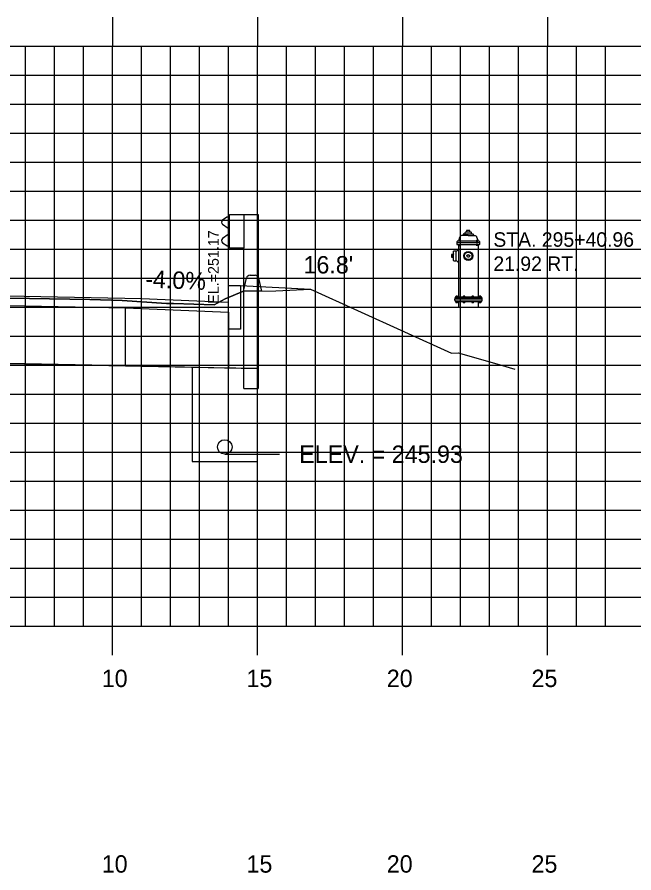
# Model space of a CAD drawing. Extents: x 859575 to 859745, y 366268 to 366378.
# Drawn here: x 859664.5 to 859685.77, y 366298.73 to 366328.24 of the extents above; entities that cross this region are included whole.
import ezdxf

# ---------------------------------------------------------------- set-up
doc = ezdxf.new("R2010")
doc.units = 0
for name, color, linetype in [('ANNOTATION', 7, 'Continuous'), ('D_Curb_Type_1_Rt', 7, 'Continuous'), ('D_Roadway_Edge_Shoulder', 7, 'Continuous'), ('D_Roadway_FinishedGrade', 7, 'Continuous'), ('D_Roadway_SubGrade', 7, 'Continuous'), ('D_Text_Monospaced', 7, 'Continuous'), ('D_Text_Standard', 7, 'Continuous'), ('H_V ANNOTATION', 7, 'Continuous'), ('JUNK COM EXC', 7, 'Continuous'), ('junk strct exc', 7, 'Continuous'), ('MAJOR', 7, 'Continuous'), ('MINOR', 7, 'Continuous'), ('PDRAIN', 7, 'Continuous'), ('S_Curb_Type_3', 7, 'Continuous'), ('S_Guardrail_Beam', 7, 'Continuous'), ('S_Roadway_Centerline', 7, 'Continuous'), ('S_Utilities_Hydrant', 7, 'Continuous')]:
    doc.layers.add(name, color=color, linetype=linetype)

msp = doc.modelspace()

# ---------------------------------------------------------------- linework, layer by layer
at = {"layer": 'D_Curb_Type_1_Rt'}
msp.add_lwpolyline([(859672.208, 366318.982), (859672.208, 366317.482), (859671.791, 366317.482), (859671.791, 366318.982)], close=True, dxfattribs=at)
at = {"layer": 'D_Roadway_Edge_Shoulder'}
msp.add_lwpolyline([(859642.824, 366318.371), (859646.797, 366318.53), (859657.797, 366318.75), (859668.797, 366318.53), (859671.791, 366318.41)], dxfattribs=at)
at = {"layer": 'D_Roadway_FinishedGrade'}
msp.add_lwpolyline([(859672.208, 366318.982), (859674.627, 366318.855)], dxfattribs=at)
at = {"layer": 'D_Roadway_SubGrade'}
for points in [[(859672.79, 366318.97), (859672.79, 366316.116), (859671.797, 366316.136)], [(859668.239, 366316.208), (859657.797, 366316.417), (859646.797, 366316.197), (859646.797, 366318.197), (859657.797, 366318.417), (859668.239, 366318.208)]]:
    msp.add_lwpolyline(points, dxfattribs=at)
msp.add_lwpolyline([(859668.239, 366318.208), (859671.791, 366318.065), (859671.791, 366316.136), (859668.239, 366316.208)], close=True, dxfattribs=at)
at = {"layer": 'D_Text_Standard'}
msp.add_lwpolyline([(859671.665, 366313.166), (859672.873, 366313.166), (859673.553, 366313.166)], dxfattribs=at)
at = {"layer": 'JUNK COM EXC'}
for points in [[(859668.239, 366316.208), (859672.79, 366316.116), (859672.79, 366318.798), (859672.312, 366318.793), (859671.68, 366318.518), (859671.301, 366318.317), (859669.901, 366318.359), (859669.657, 366318.367), (859668.133, 366318.467), (859667.018, 366318.498), (859657.962, 366318.648)], [(859657.797, 366316.417), (859668.239, 366316.208)]]:
    msp.add_lwpolyline(points, dxfattribs=at)
at = {"layer": 'junk strct exc'}
msp.add_lwpolyline([(859670.54, 366316.161), (859670.54, 366312.916), (859672.79, 366312.916), (859672.79, 366316.116)], close=True, dxfattribs=at)
at = {"layer": 'MAJOR'}
for p, q in [((859667.797, 366328.238), (859667.797, 366327.236)), ((859672.797, 366328.238), (859672.797, 366327.236)), ((859677.797, 366328.238), (859677.797, 366327.236)), ((859682.797, 366328.238), (859682.797, 366327.236)), ((859587.797, 366327.236), (859727.797, 366327.236)), ((859587.797, 366327.236), (859727.797, 366327.236)), ((859667.797, 366307.236), (859667.797, 366327.236)), ((859672.797, 366307.236), (859672.797, 366327.236)), ((859677.797, 366307.236), (859677.797, 366327.236)), ((859682.797, 366307.236), (859682.797, 366327.236)), ((859587.797, 366322.236), (859727.797, 366322.236)), ((859587.797, 366317.236), (859727.797, 366317.236)), ((859587.797, 366312.236), (859727.797, 366312.236)), ((859587.797, 366307.236), (859727.797, 366307.236)), ((859587.797, 366307.236), (859727.797, 366307.236)), ((859667.797, 366306.234), (859667.797, 366307.236)), ((859672.797, 366306.234), (859672.797, 366307.236)), ((859677.797, 366306.234), (859677.797, 366307.236)), ((859682.797, 366306.234), (859682.797, 366307.236))]:
    msp.add_line(p, q, dxfattribs=at)
at = {"layer": 'MINOR'}
for p, q in [((859664.797, 366307.236), (859664.797, 366327.236)), ((859665.797, 366307.236), (859665.797, 366327.236)), ((859666.797, 366307.236), (859666.797, 366327.236)), ((859668.797, 366307.236), (859668.797, 366327.236)), ((859669.797, 366307.236), (859669.797, 366327.236)), ((859670.797, 366307.236), (859670.797, 366327.236)), ((859671.797, 366307.236), (859671.797, 366327.236)), ((859673.797, 366307.236), (859673.797, 366327.236)), ((859674.797, 366307.236), (859674.797, 366327.236)), ((859675.797, 366307.236), (859675.797, 366327.236)), ((859676.797, 366307.236), (859676.797, 366327.236)), ((859678.797, 366307.236), (859678.797, 366327.236)), ((859679.797, 366307.236), (859679.797, 366327.236)), ((859680.797, 366307.236), (859680.797, 366327.236)), ((859681.797, 366307.236), (859681.797, 366327.236)), ((859683.797, 366307.236), (859683.797, 366327.236)), ((859684.797, 366307.236), (859684.797, 366327.236)), ((859587.797, 366326.236), (859727.797, 366326.236)), ((859587.797, 366325.236), (859727.797, 366325.236)), ((859587.797, 366324.236), (859727.797, 366324.236)), ((859587.797, 366323.236), (859727.797, 366323.236)), ((859587.797, 366321.236), (859727.797, 366321.236)), ((859587.797, 366320.236), (859727.797, 366320.236)), ((859587.797, 366319.236), (859727.797, 366319.236)), ((859587.797, 366318.236), (859727.797, 366318.236)), ((859587.797, 366316.236), (859727.797, 366316.236)), ((859587.797, 366315.236), (859727.797, 366315.236)), ((859587.797, 366314.236), (859727.797, 366314.236)), ((859587.797, 366313.236), (859727.797, 366313.236)), ((859587.797, 366311.236), (859727.797, 366311.236)), ((859587.797, 366310.236), (859727.797, 366310.236)), ((859587.797, 366309.236), (859727.797, 366309.236)), ((859587.797, 366308.236), (859727.797, 366308.236))]:
    msp.add_line(p, q, dxfattribs=at)
at = {"layer": 'PDRAIN'}
msp.add_lwpolyline([(859670.54, 366316.161), (859670.54, 366312.916), (859672.79, 366312.916), (859672.79, 366316.116)], dxfattribs=at)
msp.add_circle((859671.665, 366313.416), 0.25, dxfattribs=at)
at = {"layer": 'S_Curb_Type_3'}
for points in [[(859672.834, 366319.238), (859672.937, 366318.793), (859672.312, 366318.793), (859672.414, 366319.238)], [(859672.536, 366319.335), (859672.712, 366319.335)]]:
    msp.add_lwpolyline(points, dxfattribs=at)
for centre, start, end in [((859672.536, 366319.21), 90, 167.0054), ((859672.712, 366319.21), 12.9946, 90)]:
    msp.add_arc(centre, 0.125, start, end, dxfattribs=at)
at = {"layer": 'S_Guardrail_Beam'}
for p, q in [((859671.832, 366321.433), (859672.321, 366321.433)), ((859671.832, 366320.266), (859671.832, 366321.433)), ((859672.321, 366321.433), (859672.813, 366321.433)), ((859672.321, 366321.433), (859672.321, 366320.266)), ((859672.813, 366321.433), (859672.813, 366315.433)), ((859671.733, 366321.339), (859671.59, 366321.239)), ((859671.832, 366321.36), (859671.75, 366321.345)), ((859671.59, 366321.095), (859671.785, 366320.959)), ((859671.819, 366320.895), (859671.819, 366320.804)), ((859671.785, 366320.739), (859671.59, 366320.603)), ((859671.59, 366320.46), (859671.733, 366320.36)), ((859671.75, 366320.353), (859671.832, 366320.339)), ((859672.321, 366320.266), (859671.832, 366320.266)), ((859672.321, 366315.433), (859672.321, 366320.266)), ((859672.321, 366315.433), (859672.813, 366315.433))]:
    msp.add_line(p, q, dxfattribs=at)
for centre, major_axis, start_param, end_param in [((859671.64, 366321.167), (-0.0877, 0), 5.323254, 7.243116), ((859671.757, 366321.305), (-0.0417, 0), 4.886922, 5.323254), ((859671.74, 366320.895), (0.0789, 0), 0, 0.959931), ((859671.64, 366320.532), (-0.0877, 0), 5.323254, 7.243116), ((859671.74, 366320.804), (0.0789, 0), 5.323254, 6.283185), ((859671.757, 366320.394), (-0.0417, 0), 0.959931, 1.396263)]:
    msp.add_ellipse(centre, major_axis=major_axis, ratio=0.995501, start_param=start_param, end_param=end_param, dxfattribs=at)
at = {"layer": 'S_Roadway_Centerline'}
msp.add_lwpolyline([(859657.962, 366318.648), (859667.018, 366318.498), (859668.133, 366318.467), (859669.657, 366318.367), (859669.901, 366318.359), (859671.301, 366318.317), (859671.68, 366318.518), (859672.312, 366318.793), (859673.422, 366318.804), (859674.627, 366318.855), (859679.478, 366316.646), (859679.714, 366316.666), (859680.968, 366316.307), (859681.666, 366316.104)], dxfattribs=at)
at = {"layer": 'S_Utilities_Hydrant'}
for p, q in [((859679.763, 366320.638), (859679.724, 366320.51)), ((859680.062, 366320.709), (859679.831, 366320.709)), ((859679.909, 366320.765), (859680.214, 366320.765)), ((859679.949, 366320.806), (859679.949, 366320.765)), ((859680.158, 366320.822), (859679.966, 366320.821)), ((859680.062, 366320.709), (859680.293, 366320.709)), ((859680.174, 366320.765), (859680.174, 366320.806)), ((859680.361, 366320.638), (859680.4, 366320.51)), ((859679.668, 366320.494), (859679.668, 366320.413)), ((859680.457, 366320.453), (859679.668, 366320.453)), ((859680.44, 366320.51), (859679.684, 366320.51)), ((859679.724, 366320.397), (859679.724, 366318.591)), ((859679.743, 366320.51), (859679.743, 366320.527)), ((859679.743, 366320.373), (859679.743, 366320.397)), ((859679.772, 366320.527), (859679.772, 366320.51)), ((859679.772, 366320.397), (859679.772, 366320.373)), ((859680.353, 366320.527), (859680.353, 366320.51)), ((859680.353, 366320.397), (859680.353, 366320.373)), ((859680.381, 366320.51), (859680.381, 366320.527)), ((859680.381, 366320.373), (859680.381, 366320.397)), ((859680.4, 366320.397), (859680.4, 366318.591)), ((859679.521, 366320.051), (859679.521, 366320.048)), ((859679.521, 366320.048), (859679.521, 366319.958)), ((859679.521, 366319.955), (859679.521, 366319.958)), ((859679.531, 366320.063), (859679.531, 366319.942)), ((859679.536, 366320.064), (859679.536, 366319.942)), ((859679.556, 366320.07), (859679.548, 366320.069)), ((859679.556, 366319.845), (859679.556, 366320.162)), ((859679.572, 366320.177), (859679.633, 366320.177)), ((859679.633, 366320.177), (859679.633, 366319.828)), ((859679.64, 366320.167), (859679.633, 366320.167)), ((859679.64, 366319.834), (859679.64, 366320.172)), ((859679.724, 366320.239), (859679.724, 366320.239)), ((859679.556, 366319.935), (859679.548, 366319.937)), ((859679.633, 366319.828), (859679.571, 366319.828)), ((859679.64, 366319.839), (859679.633, 366319.839)), ((859679.724, 366319.767), (859679.724, 366319.767)), ((859680.543, 366318.534), (859679.592, 366318.534)), ((859680.543, 366318.478), (859679.592, 366318.478)), ((859679.617, 366318.591), (859680.518, 366318.591)), ((859679.652, 366318.608), (859679.652, 366318.591)), ((859679.68, 366318.591), (859679.68, 366318.608)), ((859679.903, 366318.608), (859679.903, 366318.591)), ((859679.932, 366318.591), (859679.932, 366318.608)), ((859680.204, 366318.608), (859680.204, 366318.591)), ((859680.231, 366318.591), (859680.231, 366318.608)), ((859680.455, 366318.608), (859680.455, 366318.591)), ((859680.483, 366318.591), (859680.483, 366318.608)), ((859680.518, 366318.421), (859679.617, 366318.421)), ((859679.652, 366318.421), (859679.652, 366318.397)), ((859679.68, 366318.397), (859679.68, 366318.421)), ((859679.724, 366318.421), (859679.724, 366318.255)), ((859679.903, 366318.421), (859679.903, 366318.397)), ((859679.932, 366318.397), (859679.932, 366318.421)), ((859680.204, 366318.421), (859680.204, 366318.397)), ((859680.231, 366318.397), (859680.231, 366318.421)), ((859680.4, 366318.421), (859680.4, 366318.255)), ((859680.455, 366318.421), (859680.455, 366318.397)), ((859680.483, 366318.397), (859680.483, 366318.421))]:
    msp.add_line(p, q, dxfattribs=at)
for points in [[(859680.119, 366320.821), (859680.119, 366320.877), (859680.006, 366320.877), (859680.006, 366320.821)], [(859679.893, 366320.709), (859679.893, 366320.75), (859679.894, 366320.75), (859679.893, 366320.75)], [(859680.231, 366320.75), (859680.23, 366320.75), (859680.231, 366320.75), (859680.231, 366320.709)], [(859679.683, 366320.396), (859679.683, 366320.397), (859680.441, 366320.397), (859680.441, 366320.396)], [(859679.73, 366320.51), (859679.73, 366320.527), (859679.733, 366320.531), (859679.782, 366320.531), (859679.785, 366320.527), (859679.785, 366320.51), (859679.73, 366320.51)], [(859679.785, 366320.397), (859679.785, 366320.373), (859679.782, 366320.369), (859679.733, 366320.369), (859679.73, 366320.373), (859679.73, 366320.397), (859679.785, 366320.397)], [(859679.743, 366320.376), (859679.743, 366320.36), (859679.772, 366320.36), (859679.772, 366320.373)], [(859680.395, 366320.51), (859680.395, 366320.527), (859680.391, 366320.531), (859680.342, 366320.531), (859680.338, 366320.527), (859680.338, 366320.51), (859680.395, 366320.51)], [(859680.338, 366320.397), (859680.338, 366320.373), (859680.342, 366320.369), (859680.391, 366320.369), (859680.395, 366320.373), (859680.395, 366320.397), (859680.338, 366320.397)], [(859680.381, 366320.376), (859680.381, 366320.36), (859680.353, 366320.36), (859680.353, 366320.373)], [(859680.457, 366320.413), (859680.457, 366320.493), (859680.457, 366320.494)], [(859679.521, 366320.048), (859679.485, 366320.048), (859679.485, 366319.958), (859679.521, 366319.958)], [(859680.094, 366319.959), (859680.03, 366319.959), (859680.01, 366320.02), (859680.062, 366320.058), (859680.114, 366320.02), (859680.094, 366319.959)], [(859679.694, 366318.591), (859679.694, 366318.608), (859679.69, 366318.612), (859679.642, 366318.612), (859679.638, 366318.608), (859679.638, 366318.591), (859679.694, 366318.591)], [(859679.945, 366318.591), (859679.945, 366318.608), (859679.941, 366318.612), (859679.893, 366318.612), (859679.889, 366318.608), (859679.889, 366318.591), (859679.945, 366318.591)], [(859680.246, 366318.591), (859680.246, 366318.608), (859680.242, 366318.612), (859680.193, 366318.612), (859680.189, 366318.608), (859680.189, 366318.591), (859680.246, 366318.591)], [(859680.497, 366318.591), (859680.497, 366318.608), (859680.494, 366318.612), (859680.445, 366318.612), (859680.441, 366318.608), (859680.441, 366318.591), (859680.497, 366318.591)], [(859679.638, 366318.421), (859679.638, 366318.397), (859679.642, 366318.394), (859679.69, 366318.394), (859679.694, 366318.397), (859679.694, 366318.421), (859679.638, 366318.421)], [(859679.68, 366318.4), (859679.68, 366318.384), (859679.652, 366318.384), (859679.652, 366318.397)], [(859679.889, 366318.421), (859679.889, 366318.397), (859679.893, 366318.394), (859679.941, 366318.394), (859679.945, 366318.397), (859679.945, 366318.421), (859679.889, 366318.421)], [(859679.932, 366318.4), (859679.932, 366318.384), (859679.903, 366318.384), (859679.903, 366318.397)], [(859680.189, 366318.421), (859680.189, 366318.397), (859680.193, 366318.394), (859680.242, 366318.394), (859680.246, 366318.397), (859680.246, 366318.421), (859680.189, 366318.421)], [(859680.231, 366318.4), (859680.231, 366318.384), (859680.204, 366318.384), (859680.204, 366318.397)], [(859680.441, 366318.421), (859680.441, 366318.397), (859680.445, 366318.394), (859680.494, 366318.394), (859680.497, 366318.397), (859680.497, 366318.421), (859680.441, 366318.421)], [(859680.483, 366318.4), (859680.483, 366318.384), (859680.455, 366318.384), (859680.455, 366318.397)]]:
    msp.add_lwpolyline(points, dxfattribs=at)
for radius in [0.158, 0.128]:
    msp.add_circle((859680.062, 366320.003), radius, dxfattribs=at)
for centre, radius, start, end in [((859679.855, 366320.617), 0.0943, 104.4243, 167.4801), ((859679.912, 366320.746), 0.0191, 96.9921, 168.8028), ((859679.968, 366320.802), 0.019, 96.6009, 168.4116), ((859680.156, 366320.802), 0.0191, 11.1972, 83.0079), ((859680.212, 366320.746), 0.019, 11.5319, 83.3426), ((859680.269, 366320.617), 0.0943, 12.5199, 75.5757), ((859679.687, 366320.491), 0.0191, 96.9921, 168.8028), ((859679.687, 366320.415), 0.0191, 186.9921, 258.8028), ((859679.736, 366320.522), 0.00826, 32.9144, 129.4939), ((859679.736, 366320.377), 0.00826, 230.5064, 327.0859), ((859679.757, 366320.503), 0.0282, 60.0007, 120.0007), ((859679.757, 366320.397), 0.0282, 240.0007, 300.0007), ((859679.778, 366320.522), 0.00826, 50.5064, 147.0859), ((859679.778, 366320.377), 0.00826, 212.9144, 309.4939), ((859680.346, 366320.522), 0.00826, 32.9141, 129.4936), ((859680.346, 366320.377), 0.00826, 230.5061, 327.0856), ((859680.367, 366320.503), 0.0282, 59.9993, 119.9993), ((859680.367, 366320.397), 0.0282, 239.9993, 299.9993), ((859680.388, 366320.522), 0.00826, 50.5061, 147.0856), ((859680.388, 366320.377), 0.00826, 212.9141, 309.4936), ((859680.437, 366320.491), 0.0191, 11.1972, 83.0079), ((859680.437, 366320.415), 0.0191, 281.1972, 353.0079), ((859679.53, 366320.056), 0.0104, 141.3402, 150.6422), ((859679.523, 366320.06), 0.00229, 150.6422, 170.5377), ((859679.598, 366320.048), 0.0782, 170.5377, 171.4341), ((859679.529, 366320.058), 0.00865, 171.4341, 174.1282), ((859679.534, 366320.058), 0.013, 174.1282, 177.7182), ((859679.649, 366320.053), 0.128, 177.7182, 178.8593), ((859679.606, 366320.054), 0.0857, 178.8593, 179.715), ((859680.293, 366320.05), 0.772, 179.715, 180), ((859680.293, 366319.955), 0.772, 180, 180.285), ((859679.606, 366319.952), 0.0857, 180.285, 181.1407), ((859679.649, 366319.953), 0.128, 181.1407, 182.2818), ((859679.534, 366319.948), 0.013, 182.2818, 185.8718), ((859679.529, 366319.948), 0.00865, 185.8718, 188.5659), ((859679.598, 366319.958), 0.0782, 188.5659, 189.4623), ((859679.479, 366320.097), 0.055, 321.3402, 323.1301), ((859679.509, 366320.074), 0.0174, 323.1301, 326.3099), ((859679.525, 366320.064), 0.000947, 97.125, 146.3099), ((859679.525, 366320.062), 0.00335, 71.565, 97.125), ((859679.517, 366320.038), 0.0288, 68.1986, 71.5651), ((859679.522, 366320.051), 0.0144, 63.435, 68.1986), ((859679.533, 366320.072), 0.0084, 243.4349, 251.565), ((859679.533, 366320.074), 0.0109, 251.565, 258.6901), ((859679.533, 366320.07), 0.00686, 258.6901, 270), ((859679.533, 366320.08), 0.0173, 270, 277.125), ((859679.534, 366320.07), 0.00682, 277.125, 294.444), ((859679.536, 366320.066), 0.00252, 294.444, 323.1301), ((859679.545, 366320.059), 0.00939, 126.8699, 135), ((859679.545, 366320.059), 0.00939, 135, 143.1301), ((859679.542, 366320.064), 0.00357, 105.7372, 126.8699), ((859679.572, 366319.955), 0.117, 102.0619, 105.7372), ((859679.574, 366320.158), 0.0191, 96.9921, 168.8028), ((859679.626, 366320.275), 0.105, 277.4234, 339.5299), ((859679.523, 366319.945), 0.00229, 189.4623, 209.3578), ((859679.53, 366319.949), 0.0104, 209.3578, 218.6598), ((859679.479, 366319.909), 0.055, 36.8699, 38.6598), ((859679.509, 366319.931), 0.0174, 33.6901, 36.8699), ((859679.525, 366319.941), 0.000947, 213.6901, 262.875), ((859679.525, 366319.944), 0.00335, 262.875, 288.435), ((859679.517, 366319.968), 0.0288, 288.4349, 291.8014), ((859679.522, 366319.954), 0.0144, 291.8014, 296.565), ((859679.533, 366319.934), 0.0084, 108.4349, 116.5651), ((859679.533, 366319.932), 0.0109, 101.3099, 108.4349), ((859679.533, 366319.936), 0.00686, 90, 101.3099), ((859679.533, 366319.925), 0.0173, 82.875, 90), ((859679.534, 366319.936), 0.00682, 65.556, 82.875), ((859679.536, 366319.94), 0.00252, 36.8699, 65.556), ((859679.545, 366319.947), 0.00939, 216.8699, 225), ((859679.545, 366319.947), 0.00939, 225, 233.1301), ((859679.542, 366319.942), 0.00357, 233.1301, 254.2628), ((859679.572, 366320.051), 0.117, 254.2628, 257.9381), ((859679.574, 366319.847), 0.0192, 186.7328, 258.5435), ((859679.626, 366319.73), 0.105, 20.4701, 82.5766), ((859679.73, 366318.506), 0.141, 143.1301, 216.8699), ((859679.645, 366318.603), 0.00826, 32.9141, 129.4936), ((859679.666, 366318.583), 0.0282, 59.9993, 119.9993), ((859679.687, 366318.603), 0.00826, 50.5061, 147.0856), ((859679.896, 366318.603), 0.00826, 32.9141, 129.4936), ((859679.917, 366318.583), 0.0282, 59.9993, 119.9993), ((859679.938, 366318.603), 0.00826, 50.5061, 147.0856), ((859680.197, 366318.603), 0.00826, 32.9141, 129.4936), ((859680.218, 366318.583), 0.0282, 59.9993, 119.9993), ((859680.239, 366318.603), 0.00826, 50.5061, 147.0856), ((859680.448, 366318.603), 0.00826, 32.9141, 129.4936), ((859680.469, 366318.583), 0.0282, 59.9993, 119.9993), ((859680.49, 366318.603), 0.00826, 50.5061, 147.0856), ((859680.405, 366318.506), 0.141, 323.1301, 36.8699), ((859679.645, 366318.402), 0.00826, 230.5061, 327.0856), ((859679.666, 366318.422), 0.0282, 239.9993, 299.9993), ((859679.687, 366318.402), 0.00826, 212.9141, 309.4936), ((859679.896, 366318.402), 0.00826, 230.5061, 327.0856), ((859679.917, 366318.422), 0.0282, 239.9993, 299.9993), ((859679.938, 366318.402), 0.00826, 212.9141, 309.4936), ((859680.197, 366318.402), 0.00826, 230.5061, 327.0856), ((859680.218, 366318.422), 0.0282, 239.9993, 299.9993), ((859680.239, 366318.402), 0.00826, 212.9141, 309.4936), ((859680.448, 366318.402), 0.00826, 230.5061, 327.0856), ((859680.469, 366318.422), 0.0282, 239.9993, 299.9993), ((859680.49, 366318.402), 0.00826, 212.9141, 309.4936)]:
    msp.add_arc(centre, radius, start, end, dxfattribs=at)

# ---------------------------------------------------------------- texts
at = {"layer": 'ANNOTATION'}
msp.add_text('-4.0%', height=0.6, rotation=357.6944, dxfattribs=at).set_placement((859668.911, 366318.915))
at = {"layer": 'D_Text_Monospaced'}
for s, height, p in [('STA. 295+40.96', 0.49998, (859680.927, 366320.319)), ('21.92 RT.', 0.5, (859680.927, 366319.485))]:
    msp.add_text(s, height=height, dxfattribs=at).set_placement(p)
at = {"layer": 'D_Text_Standard'}
msp.add_text(' EL.=251.17', height=0.36848, rotation=90, dxfattribs=at).set_placement((859671.458, 366318.216))
for s, p in [("16.8'", (859674.379, 366319.398)), ('ELEV. = 245.93', (859674.233, 366312.866))]:
    msp.add_text(s, height=0.6, dxfattribs=at).set_placement(p)
at = {"layer": 'H_V ANNOTATION'}
for s, p in [('10', (859667.423, 366305.136)), ('15', (859672.415, 366305.136)), ('20', (859677.251, 366305.136)), ('25', (859682.243, 366305.136)), ('10', (859667.423, 366298.736)), ('15', (859672.415, 366298.736)), ('20', (859677.251, 366298.736)), ('25', (859682.243, 366298.736))]:
    msp.add_text(s, height=0.6, dxfattribs=at).set_placement(p)

doc.saveas('drawing.dxf')
